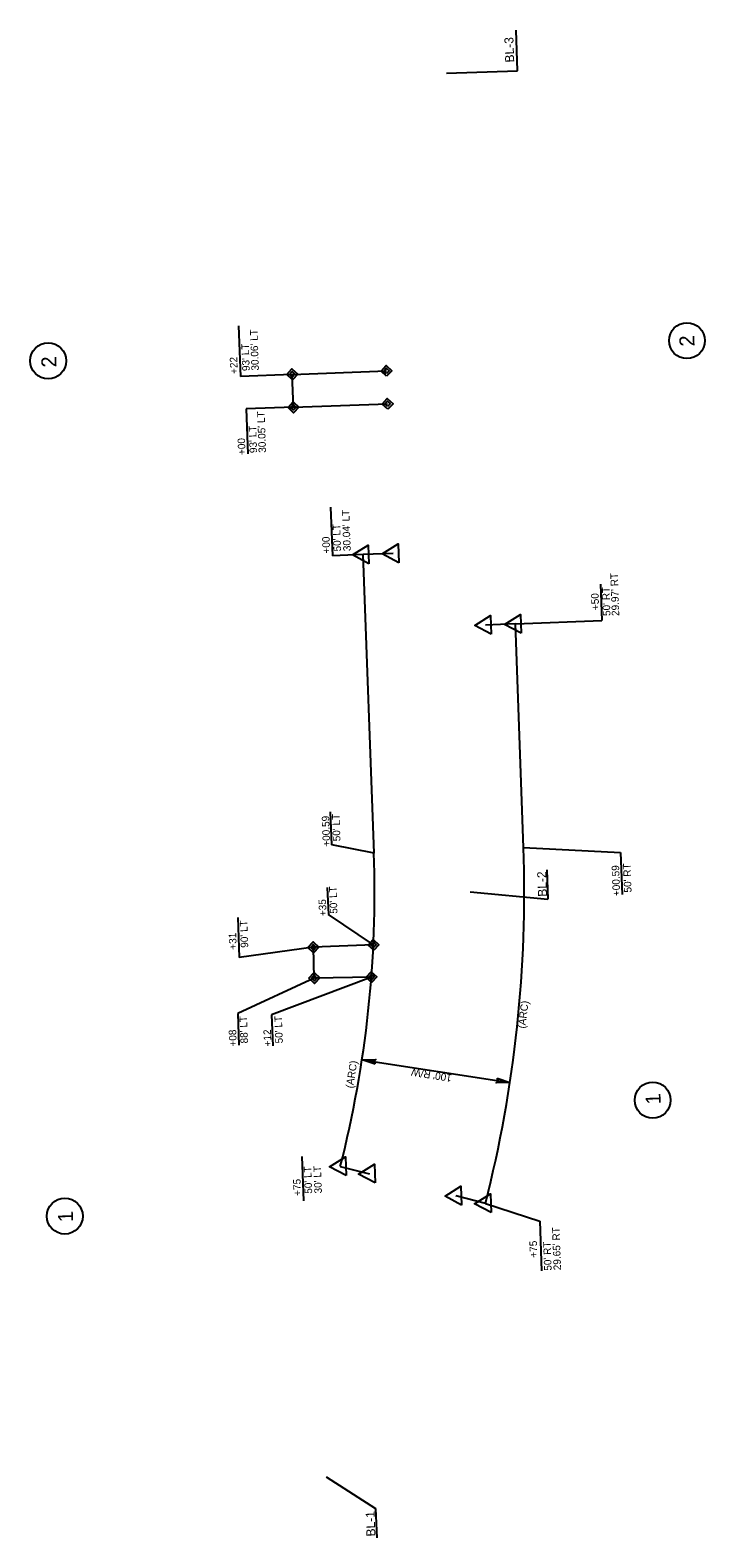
# Model space of a CAD drawing. Extents: x 2065634 to 2066229, y 144790 to 146885.
# Drawn here: x 2065778 to 2066229, y 144790 to 145797 of the extents above; entities that cross this region are included whole.
import ezdxf

# ---------------------------------------------------------------- set-up
doc = ezdxf.new("R2010")
doc.units = 0
for name, color, linetype in [('Prop Dimension', 7, 'Continuous'), ('Prop DSN Text', 7, 'Continuous'), ('Prop Easement Permanent Utility', 7, 'Continuous'), ('Prop Easement Permanent Utility Station Offsets', 7, 'Continuous'), ('Prop Parcel Number CELL', 7, 'Continuous'), ('Prop Parcel Number Text', 7, 'Continuous'), ('Prop ROW Marker CELL', 7, 'Continuous'), ('Prop ROW Permanent Easement CELL', 7, 'Continuous'), ('Prop ROW RW Lines', 7, 'Continuous'), ('Prop ROW Station Offsets', 7, 'Continuous'), ('Prop Terminator CELL', 7, 'Continuous')]:
    doc.layers.add(name, color=color, linetype=linetype)

msp = doc.modelspace()

# ---------------------------------------------------------------- linework, layer by layer
at = {"layer": 'Prop Dimension'}
msp.add_line((2065999.5, 145109.4), (2066098.3, 145094.4), dxfattribs=at)
at = {"layer": 'Prop DSN Text'}
for p, q in [((2066103.4, 145770.1), (2066102.5, 145797.2)), ((2066056, 145768.4), (2066103.4, 145770.1)), ((2066123, 145236.3), (2066123.7, 145216.8)), ((2066071.8, 145221.6), (2066123.7, 145216.8)), ((2065975.6, 144831), (2066008.6, 144809.7)), ((2066008.6, 144809.7), (2066009.3, 144790.2))]:
    msp.add_line(p, q, dxfattribs=at)
at = {"layer": 'Prop Easement Permanent Utility'}
for p, q in [((2065952.9, 145567.3), (2066015.8, 145569.6)), ((2065953.7, 145545.3), (2065952.9, 145567.3)), ((2065953.7, 145545.3), (2066016.6, 145547.6)), ((2066007.1, 145186.2), (2065967, 145184.6)), ((2065967.6, 145164.1), (2065967, 145184.6)), ((2066005.8, 145164.7), (2065967.6, 145164.1))]:
    msp.add_line(p, q, dxfattribs=at)
at = {"layer": 'Prop Easement Permanent Utility Station Offsets'}
for p, q in [((2065917, 145599.7), (2065918.2, 145565.9)), ((2065952.9, 145567.3), (2065918.2, 145565.9)), ((2065953.7, 145545.3), (2065922.1, 145544.3)), ((2065922.1, 145544.3), (2065923.2, 145514.3)), ((2065976.3, 145224.6), (2065977, 145206.6)), ((2065916.5, 145204.6), (2065917.5, 145177.7)), ((2066007.1, 145186.2), (2065977, 145206.6)), ((2065967, 145184.6), (2065917.5, 145177.7)), ((2065967.6, 145164.1), (2065916.6, 145140.4)), ((2066005.8, 145164.7), (2065939.1, 145139.6)), ((2065916.6, 145140.4), (2065917.3, 145119.2)), ((2065939.1, 145139.6), (2065939.9, 145118.9))]:
    msp.add_line(p, q, dxfattribs=at)
at = {"layer": 'Prop Parcel Number CELL'}
for p, q in [((2066216.6, 145589.8), (2066216.6, 145589.8)), ((2065789.8, 145576.3), (2065789.8, 145576.3)), ((2066193.7, 145082.5), (2066193.7, 145082.5)), ((2065800.9, 145005.1), (2065800.9, 145005.1))]:
    msp.add_line(p, q, dxfattribs=at)
for centre in [(2066216.6, 145589.8), (2065789.8, 145576.3), (2066193.7, 145082.5), (2065800.9, 145005.1)]:
    msp.add_circle(centre, 12, dxfattribs=at)
at = {"layer": 'Prop ROW Marker CELL'}
for p, q in [((2066000.3, 145446.9), (2066000.3, 145446.9)), ((2066020.2, 145447.6), (2066020.2, 145447.6)), ((2066082, 145399.8), (2066082, 145399.8)), ((2066102, 145400.6), (2066102, 145400.6)), ((2065985, 145038.2), (2065985, 145038.2)), ((2066004.4, 145033.3), (2066004.4, 145033.3)), ((2066062.2, 145018.6), (2066062.2, 145018.6)), ((2066081.9, 145013.6), (2066081.9, 145013.6))]:
    msp.add_line(p, q, dxfattribs=at)
for points in [[(2066004.1, 145440.8), (2065993.1, 145446.7), (2066003.6, 145453.3)], [(2066024, 145441.5), (2066013, 145447.4), (2066023.6, 145454)], [(2066085.8, 145393.7), (2066074.8, 145399.6), (2066085.3, 145406.2)], [(2066105.8, 145394.4), (2066094.8, 145400.3), (2066105.4, 145406.9)], [(2065988.9, 145032.1), (2065977.8, 145038), (2065988.4, 145044.6)], [(2066008.2, 145027.2), (2065997.2, 145033), (2066007.8, 145039.7)], [(2066066, 145012.5), (2066055, 145018.3), (2066065.6, 145025)], [(2066085.8, 145007.4), (2066074.7, 145013.3), (2066085.3, 145019.9)]]:
    msp.add_lwpolyline(points, close=True, dxfattribs=at)
at = {"layer": 'Prop ROW Permanent Easement CELL'}
for p, q in [((2065952.9, 145567.3), (2065952.9, 145567.3)), ((2066015.8, 145569.6), (2066015.8, 145569.6)), ((2065953.7, 145545.3), (2065953.7, 145545.3)), ((2066016.6, 145547.6), (2066016.6, 145547.6)), ((2065967, 145184.6), (2065967, 145184.6)), ((2066007.1, 145186.2), (2066007.1, 145186.2)), ((2065967.6, 145164.1), (2065967.6, 145164.1)), ((2066005.8, 145164.7), (2066005.8, 145164.7))]:
    msp.add_line(p, q, dxfattribs=at)
for points in [[(2066015.9, 145566), (2066012.2, 145569.4), (2066015.6, 145573.2), (2066019.4, 145569.7)], [(2065956.5, 145567.4), (2065953, 145563.7), (2065949.3, 145567.2), (2065952.7, 145570.9)], [(2065954.7, 145567.4), (2065952.9, 145565.5), (2065951.1, 145567.2), (2065952.8, 145569.1)], [(2066015.8, 145567.8), (2066014, 145569.5), (2066015.7, 145571.4), (2066017.6, 145569.6)], [(2065950.1, 145545.2), (2065953.5, 145548.9), (2065957.3, 145545.4), (2065953.8, 145541.7)], [(2065951.9, 145545.2), (2065953.6, 145547.1), (2065955.5, 145545.4), (2065953.7, 145543.5)], [(2066016.7, 145544), (2066013, 145547.4), (2066016.4, 145551.2), (2066020.2, 145547.7)], [(2066016.6, 145545.8), (2066014.8, 145547.5), (2066016.5, 145549.4), (2066018.4, 145547.6)], [(2065970.6, 145184.7), (2065967.1, 145181), (2065963.4, 145184.4), (2065966.9, 145188.2)], [(2065968.8, 145184.6), (2065967.1, 145182.8), (2065965.2, 145184.5), (2065966.9, 145186.4)], [(2066007.3, 145182.6), (2066003.5, 145186.1), (2066007, 145189.8), (2066010.7, 145186.3)], [(2066007.2, 145184.4), (2066005.3, 145186.2), (2066007.1, 145188), (2066008.9, 145186.3)], [(2065964, 145163.9), (2065967.5, 145167.7), (2065971.2, 145164.2), (2065967.8, 145160.5)], [(2065965.8, 145164), (2065967.6, 145165.9), (2065969.4, 145164.1), (2065967.7, 145162.3)], [(2066005.9, 145161.1), (2066002.2, 145164.6), (2066005.7, 145168.3), (2066009.4, 145164.8)], [(2066005.9, 145162.9), (2066004, 145164.7), (2066005.7, 145166.5), (2066007.6, 145164.8)]]:
    msp.add_lwpolyline(points, close=True, dxfattribs=at)
at = {"layer": 'Prop ROW RW Lines'}
for p, q in [((2066020.2, 145447.6), (2066000.3, 145446.9)), ((2066007.5, 145247.6), (2066000.3, 145446.9)), ((2066102, 145400.6), (2066082, 145399.8)), ((2066107.4, 145251.3), (2066102, 145400.6)), ((2065985, 145038.2), (2066004.4, 145033.3)), ((2066081.9, 145013.6), (2066062.2, 145018.6))]:
    msp.add_line(p, q, dxfattribs=at)
for radius in [840, 740]:
    msp.add_arc((2065267.9, 145220.9), radius, 345.7091, 2.0702, dxfattribs=at)
at = {"layer": 'Prop ROW Station Offsets'}
for p, q in [((2065978.5, 145478.6), (2065979.7, 145446)), ((2066000.3, 145446.9), (2065979.7, 145446)), ((2066158.8, 145427.2), (2066159.7, 145402.8)), ((2066102, 145400.6), (2066159.7, 145402.8)), ((2065979.3, 145253), (2065978.5, 145275.1)), ((2066007.5, 145247.6), (2065979.3, 145253)), ((2066107.4, 145251.3), (2066172.2, 145248)), ((2066172.2, 145248), (2066173.2, 145219.9)), ((2065959.3, 145044.8), (2065960.4, 145015.2)), ((2066081.9, 145013.6), (2066118.3, 145001.7)), ((2066118.3, 145001.7), (2066119.5, 144968.5))]:
    msp.add_line(p, q, dxfattribs=at)
at = {"layer": 'Prop Terminator CELL'}
for points in [[(2066008.2, 145106.5), (2065999.5, 145109.4), (2066008.7, 145109.6), (2066007.3, 145108.2)], [(2066089.7, 145097.2), (2066098.3, 145094.4), (2066089.2, 145094.1), (2066090.5, 145095.5)]]:
    msp.add_lwpolyline(points, close=True, dxfattribs=at)

# ---------------------------------------------------------------- texts
at = {"layer": 'Prop Dimension'}
msp.add_text("100' R/W", height=5, rotation=170.9559, dxfattribs=at).set_placement((2066059.8, 145099.6))
at = {"layer": 'Prop DSN Text'}
for s, p in [('BL-3', (2066101.2, 145775.7)), ('BL-2', (2066123.1, 145218.5)), ('BL-1', (2066008.5, 144791.2))]:
    msp.add_text(s, height=6, rotation=92.0702, dxfattribs=at).set_placement(p)
at = {"layer": 'Prop Easement Permanent Utility Station Offsets'}
for s, p in [("30.06' LT", (2065930.6, 145569.9)), ("93' LT", (2065924.5, 145569.6)), ('+22', (2065916.5, 145567.7)), ("93' LT", (2065929.4, 145514.8)), ("30.05' LT", (2065935.4, 145515)), ('+00', (2065921.7, 145513.5)), ("50' LT", (2065983.1, 145207.1)), ('+35', (2065975.8, 145205.5)), ("90' LT", (2065923.5, 145184.4)), ('+31', (2065915.8, 145183.1)), ("88' LT", (2065923.3, 145120.5)), ("50' LT", (2065946.6, 145120.5)), ('+08', (2065915.8, 145118.4)), ('+12', (2065939, 145118.5))]:
    msp.add_text(s, height=5, rotation=92.0702, dxfattribs=at).set_placement(p)
at = {"layer": 'Prop Parcel Number Text'}
for s, p in [('2', (2066221.7, 145586.1)), ('2', (2065795.4, 145572.1)), ('1', (2066199.1, 145079.8)), ('1', (2065806.5, 145001.2))]:
    msp.add_text(s, height=10, rotation=92.0702, dxfattribs=at).set_placement(p)
at = {"layer": 'Prop ROW Station Offsets'}
for s, rotation, p in [("30.04' LT", 92.0702, (2065992, 145449.3)), ("50' LT", 92.0702, (2065985.5, 145449.1)), ('+00', 92.0702, (2065978.2, 145447.7)), ("29.97' RT", 92.0702, (2066171.4, 145406)), ("50' RT", 92.0702, (2066165.5, 145406)), ('+50', 92.0702, (2066157.9, 145409.9)), ('+00.59', 92.0702, (2065978.3, 145251.9)), ("50' LT", 92.0702, (2065985.1, 145255.5)), ('+00.59', 92.0702, (2066172, 145218.9)), ("50' RT", 92.0702, (2066179.6, 145221.3)), ('(ARC)', 82.7146, (2066108.5, 145130.2)), ('(ARC)', 80.9619, (2065993.5, 145090.2)), ('+75', 92.0702, (2065958.8, 145018.7)), ("50' LT", 92.0702, (2065966.2, 145020.1)), ("30' LT", 92.0702, (2065972.7, 145020.3)), ("29.65' RT", 92.0702, (2066132.5, 144969)), ('+75', 92.0702, (2066116.7, 144977.4)), ("50' RT", 92.0702, (2066126.2, 144968.7))]:
    msp.add_text(s, height=5, rotation=rotation, dxfattribs=at).set_placement(p)

doc.saveas('drawing.dxf')
